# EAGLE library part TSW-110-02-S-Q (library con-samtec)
THROUGH-HOLE .025" SQ POST HEADER Source: Samtec TSW.pdf
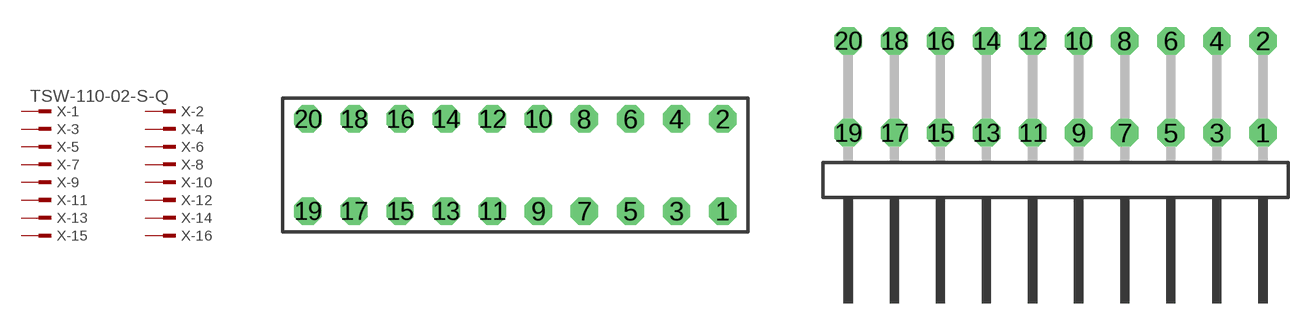
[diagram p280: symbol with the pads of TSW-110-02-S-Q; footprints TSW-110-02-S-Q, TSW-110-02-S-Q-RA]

Designator prefix X; gates -1=MPINV -2=MPIN -3=MPIN -4=MPIN -5=MPIN -6=MPIN -7=MPIN -8=MPIN -9=MPIN -10=MPIN -11=MPIN -12=MPIN -13=MPIN -14=MPIN -15=MPIN -16=MPIN -17=MPIN -18=MPIN -19=MPIN -20=MPIN

## TSW-110-02-S-Q (OC_FARNELL: unknown; OC_NEWARK: unknown)  [TSW-110-02-S-Q]
1  -1:1  pas
2  -2:1  pas
3  -3:1  pas
4  -4:1  pas
5  -5:1  pas
6  -6:1  pas
7  -7:1  pas
8  -8:1  pas
9  -9:1  pas
10  -10:1  pas
11  -11:1  pas
12  -12:1  pas
13  -13:1  pas
14  -14:1  pas
15  -15:1  pas
16  -16:1  pas
17  -17:1  pas
18  -18:1  pas
19  -19:1  pas
20  -20:1  pas

## TSW-110-02-S-Q-RA (OC_FARNELL: unknown; OC_NEWARK: unknown)  [TSW-110-02-S-Q-RA]
Pads as for TSW-110-02-S-Q

## Footprint TSW-110-02-S-Q (pad centres in mm)
THROUGH-HOLE .025" SQ POST HEADER Source: Samtec TSW.pdf
drill 1 pad 1.5 octagon: 1 11.43,-2.54; 2 11.43,2.54; 3 8.89,-2.54; 4 8.89,2.54; 5 6.35,-2.54; 6 6.35,2.54; 7 3.81,-2.54; 8 3.81,2.54; 9 1.27,-2.54; 10 1.27,2.54; 11 -1.27,-2.54; 12 -1.27,2.54; 13 -3.81,-2.54; 14 -3.81,2.54; 15 -6.35,-2.54; 16 -6.35,2.54; 17 -8.89,-2.54; 18 -8.89,2.54; 19 -11.43,-2.54; 20 -11.43,2.54

## Footprint TSW-110-02-S-Q-RA (pad centres in mm)
THROUGH-HOLE .025" SQ POST HEADER Source: Samtec TSW.pdf
drill 1 pad 1.5 octagon: 1 11.43,1.524; 2 11.43,6.604; 3 8.89,1.524; 4 8.89,6.604; 5 6.35,1.524; 6 6.35,6.604; 7 3.81,1.524; 8 3.81,6.604; 9 1.27,1.524; 10 1.27,6.604; 11 -1.27,1.524; 12 -1.27,6.604; 13 -3.81,1.524; 14 -3.81,6.604; 15 -6.35,1.524; 16 -6.35,6.604; 17 -8.89,1.524; 18 -8.89,6.604; 19 -11.43,1.524; 20 -11.43,6.604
